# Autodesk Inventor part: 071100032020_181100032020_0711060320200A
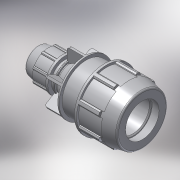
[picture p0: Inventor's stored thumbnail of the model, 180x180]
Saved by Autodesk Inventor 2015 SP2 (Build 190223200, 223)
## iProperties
Created: 2017-02
Part Number: 071100032020_181100032020_0711060320200A
Material: PVC-Piping
Description: PLASSON REDUCING COUPLER 32-20
Document SubType Name: Modeling
Designer: KIM
Mass: 92.6774 g
Surface Area: 199.44 cm^2
Volume: 66.1981 cm^3
Density: 1.4 g/cm^3
Appearance: Smooth - White
Author: KIM
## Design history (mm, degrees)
derived "07110.ipt"
feature "Solid1::07110.ipt"
tag "TaggingFeature1"
body "Solid1"
other parameters: "d2" = 32, "d4" = 11.66667, "d7" = 64, "d11" = 2, "d12" = 51.2, "d13" = 120 deg, "d14" = 48, "d15" = 12 deg, "d16" = 57.6, "d18" = 1.6, "d19" = 35 deg, "d20" = 17.5 deg, "d21" = 59.52, "d23" = 0, "d25" = 360 deg, "d27" = 1.28, "d42" = 30.8, "d46" = 0.96, "d53" = 12 deg, "d54" = 67, "d58" = 28.8, "d59" = 18, "d60" = 43.2, "d61" = 38.4, "d62" = 14, "d63" = 22.4, "d64" = 120 deg, "d65" = 48, "d74" = 44.64, "d75" = 35 deg, "d76" = 17.5 deg, "d78" = 0, "d80" = 360 deg, "d85" = 0.96, "d88" = 0.4, "d93" = 57, "d94" = 44.8, "d97" = 2.33333, "d98" = 3.2, "d99" = 0, "d100" = 2.56, "d102" = 360 deg, "d104" = 2, "d106" = 0, "d107" = 3.2, "d108" = 0, "d109" = 3.2, "d110" = 0, "d_" = 32, "E_" = 64, "l_" = 67, "E_1" = 48, "l_1" = 57, "d96" = 7
